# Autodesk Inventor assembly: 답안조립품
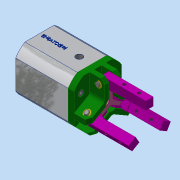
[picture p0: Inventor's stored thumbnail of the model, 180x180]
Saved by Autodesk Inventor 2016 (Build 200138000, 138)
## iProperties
Created: 2020-02
Part Number: 답안조립품
Document SubType Name: Assembly
Designer: Administrator
Author: Administrator
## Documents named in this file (13)
- C:\Users\Administrator\Desktop\700206V1004\답안조립품.iam
- C:\Users\Administrator\Desktop\700206V1004\본체.ipt
- C:\Users\Administrator\Desktop\700206V1004\본체헤드.ipt
- C:\Users\Administrator\Desktop\700206V1004\볼트 M4.ipt
- C:\Users\Administrator\Desktop\700206V1004\피스톤.ipt
- C:\Users\Administrator\Desktop\700206V1004\핀 A.ipt
- C:\Users\Administrator\Desktop\700206V1004\핀 B.ipt
- C:\Users\Administrator\Desktop\700206V1004\핑거.ipt
- C:\Users\Administrator\Desktop\700206V1004\E링.ipt
- C:\Users\Administrator\Desktop\700206V1004\O-RING 12x16.ipt
- C:\Users\Administrator\Desktop\700206V1004\O-RING 18x22.ipt
- C:\Users\Administrator\Desktop\700206V1004\O-RING 34x40.ipt
- C:\Users\Administrator\Desktop\700206V1004\로드.ipt
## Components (20 placed, 8 different names)
1. 피스톤:1
2. 핀 B:1 — 플러쉬:2
3. 핑거:1 — 플러쉬:3
4. E링:1
5. O-RING 12x16:1
6. O-RING 18x22:1
7. O-RING 34x40:2
8. 핑거:2 — 플러쉬:2
9. 핑거:3 — 플러쉬:1
10. 핀 B:2 — 플러쉬:1
11. 핀 B:3 — 플러쉬:3
12. E링:2
13. 핀 A:3
14. E링:3
15. E링:4
16. 핀 A:4
17. E링:5
18. E링:6
19. 핀 A:5
20. O-RING 34x40:3
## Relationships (3: Flush 3)
- 플러쉬:1 [Flush]: 핑거:3 ↔ 핀 B:2
- 플러쉬:2 [Flush]: 핀 B:1 ↔ 핑거:2
- 플러쉬:3 [Flush]: 핑거:1 ↔ 핀 B:3
## Named parameters: d21_d19 = 0, d22_d20 = 0, d23_d19 = 0, d24_d20 = 0
